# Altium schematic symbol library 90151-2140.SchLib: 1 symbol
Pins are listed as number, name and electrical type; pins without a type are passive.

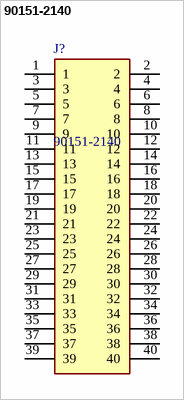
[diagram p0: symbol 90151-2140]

## 90151-2140
designator J?
Headers & Wire Housings C-Grid PCB Conn DR V onn DR Vt Tn-A 40Ckt; Manufacturer_Name: Molex; Geometry.Height: 8.7mm
footprint RHDR40W70P254_2X20_5065X498X870P
pins: 1, 2, 3, 4, 5, 6, 7, 8, 9, 10, 11, 12, 13, 14, 15, 16, 17, 18, 19, 20, 21, 22, 23, 24, 25, 26, 27, 28, 29, 30, 31, 32, 33, 34, 35, 36, 37, 38, 39, 40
